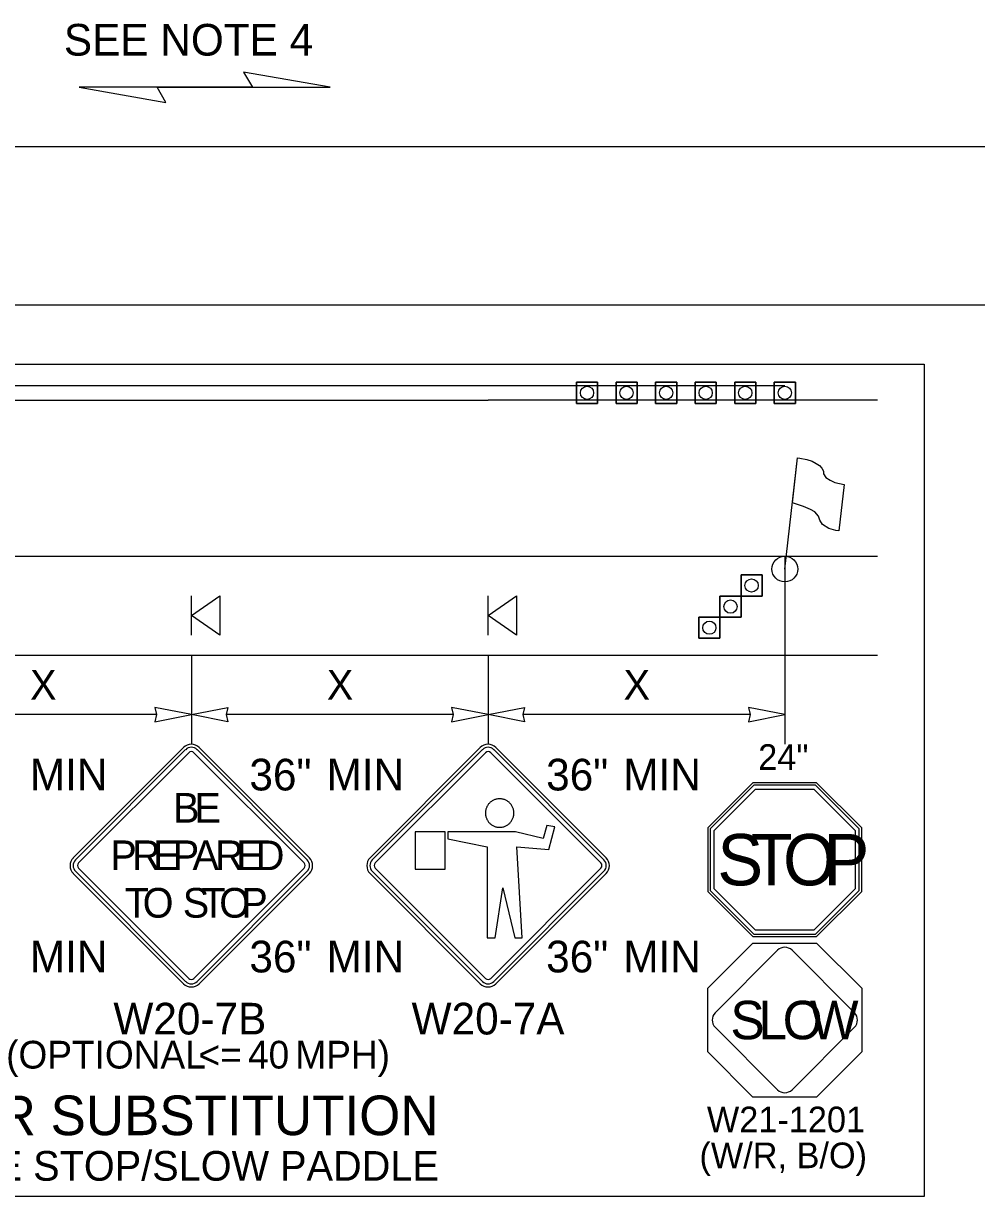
# Model space of a CAD drawing. Extents: x 99999.1 to 100095.7, y 99995 to 100010.7.
# Drawn here: x 100046.834 to 100049.243, y 100003.48 to 100006.443 of the extents above; entities that cross this region are included whole.
import ezdxf

# ---------------------------------------------------------------- set-up
doc = ezdxf.new("R2010")
doc.units = 0
for name, color, linetype in [('RD_ED_ShoulderPavedEdge', 7, 'Continuous'), ('RD_MK_LineDblYellowCenter', 7, 'Continuous'), ('RD_MK_LineEdgeWhite', 7, 'Continuous'), ('RD_MK_LineNoPass', 7, 'Continuous'), ('RD_MK_LineSkipCenter', 7, 'Continuous'), ('SH_DE_DetailHeading2Text', 7, 'Continuous'), ('TR_SN_ConstructionSigns', 7, 'Continuous'), ('TR_WZ_FlaggingStation', 7, 'Continuous'), ('TR_WZ_PortableSignMountBlk-Org', 7, 'Continuous'), ('TR_WZ_TrafficCone', 7, 'Continuous'), ('TR_WZ_WorkZoneDetails', 7, 'Continuous'), ('TR_WZ_WorkZoneTextCurrent', 7, 'Continuous')]:
    doc.layers.add(name, color=color, linetype=linetype)

msp = doc.modelspace()

# ---------------------------------------------------------------- linework, layer by layer
at = {"layer": 'RD_ED_ShoulderPavedEdge'}
for p, q in [((100040.1076, 100005.7323), (100055.6424, 100005.7323)), ((100045.4994, 100004.8473), (100048.9925, 100004.8473))]:
    msp.add_line(p, q, dxfattribs=at)
at = {"layer": 'RD_MK_LineDblYellowCenter'}
for p, q in [((100045.4994, 100005.5286), (100048.0081, 100005.5286)), ((100045.4994, 100005.4911), (100048.0081, 100005.4911))]:
    msp.add_line(p, q, dxfattribs=at)
at = {"layer": 'RD_MK_LineEdgeWhite'}
for p, q in [((100040.1076, 100006.1323), (100055.6424, 100006.1323)), ((100045.4994, 100005.0973), (100048.9925, 100005.0973))]:
    msp.add_line(p, q, dxfattribs=at)
at = {"layer": 'RD_MK_LineNoPass'}
msp.add_line((100048.0081, 100005.5286), (100048.7581, 100005.5286), dxfattribs=at)
at = {"layer": 'RD_MK_LineSkipCenter'}
msp.add_lwpolyline([(100048.9925, 100005.4911), (100048.0081, 100005.4911)], dxfattribs=at)
at = {"layer": 'TR_SN_ConstructionSigns'}
for p, q in [((100047.2382, 100004.6141), (100046.9598, 100004.3357)), ((100047.2437, 100004.6086), (100046.9653, 100004.3301)), ((100047.5509, 100004.3301), (100047.2724, 100004.6086)), ((100047.5564, 100004.3357), (100047.278, 100004.6141)), ((100047.9882, 100004.6141), (100047.7098, 100004.3357)), ((100047.9937, 100004.6086), (100047.7153, 100004.3301)), ((100048.3009, 100004.3301), (100048.0224, 100004.6086)), ((100048.3064, 100004.3357), (100048.028, 100004.6141)), ((100046.973, 100004.3224), (100047.2515, 100004.6008)), ((100047.2647, 100004.6008), (100047.5431, 100004.3224)), ((100047.723, 100004.3224), (100048.0015, 100004.6008)), ((100048.0147, 100004.6008), (100048.2931, 100004.3224)), ((100048.6775, 100004.5251), (100048.5636, 100004.4113)), ((100048.68, 100004.5191), (100048.5697, 100004.4087)), ((100048.8385, 100004.5251), (100048.6775, 100004.5251)), ((100048.836, 100004.5191), (100048.68, 100004.5191)), ((100048.9463, 100004.4087), (100048.836, 100004.5191)), ((100048.9524, 100004.4113), (100048.8385, 100004.5251)), ((100048.5798, 100004.4046), (100048.6842, 100004.5089)), ((100048.6842, 100004.5089), (100048.8318, 100004.5089)), ((100048.8318, 100004.5089), (100048.9362, 100004.4046)), ((100048.0025, 100004.458), (100048.0021, 100004.4561)), ((100048.0031, 100004.4598), (100048.0025, 100004.458)), ((100048.0037, 100004.4616), (100048.0031, 100004.4598)), ((100048.0045, 100004.4634), (100048.0037, 100004.4616)), ((100048.0053, 100004.4651), (100048.0045, 100004.4634)), ((100048.0062, 100004.4668), (100048.0053, 100004.4651)), ((100048.0073, 100004.4685), (100048.0062, 100004.4668)), ((100048.0083, 100004.47), (100048.0073, 100004.4685)), ((100048.0095, 100004.4715), (100048.0083, 100004.47)), ((100048.0108, 100004.473), (100048.0095, 100004.4715)), ((100048.0122, 100004.4743), (100048.0108, 100004.473)), ((100048.0135, 100004.4756), (100048.0122, 100004.4743)), ((100048.015, 100004.4768), (100048.0135, 100004.4756)), ((100048.0165, 100004.478), (100048.015, 100004.4768)), ((100048.0182, 100004.479), (100048.0165, 100004.478)), ((100048.0198, 100004.48), (100048.0182, 100004.479)), ((100048.0215, 100004.4809), (100048.0198, 100004.48)), ((100048.0232, 100004.4817), (100048.0215, 100004.4809)), ((100048.025, 100004.4824), (100048.0232, 100004.4817)), ((100048.0269, 100004.483), (100048.025, 100004.4824)), ((100048.0287, 100004.4835), (100048.0269, 100004.483)), ((100048.0306, 100004.4839), (100048.0287, 100004.4835)), ((100048.0325, 100004.4842), (100048.0306, 100004.4839)), ((100048.0344, 100004.4844), (100048.0325, 100004.4842)), ((100048.0363, 100004.4845), (100048.0344, 100004.4844)), ((100048.0382, 100004.4845), (100048.0363, 100004.4845)), ((100048.0401, 100004.4844), (100048.0382, 100004.4845)), ((100048.0421, 100004.4842), (100048.0401, 100004.4844)), ((100048.0439, 100004.4839), (100048.0421, 100004.4842)), ((100048.0458, 100004.4835), (100048.0439, 100004.4839)), ((100048.0476, 100004.483), (100048.0458, 100004.4835)), ((100048.0495, 100004.4824), (100048.0476, 100004.483)), ((100048.0513, 100004.4817), (100048.0495, 100004.4824)), ((100048.053, 100004.4809), (100048.0513, 100004.4817)), ((100048.0547, 100004.48), (100048.053, 100004.4809)), ((100048.0564, 100004.479), (100048.0547, 100004.48)), ((100048.058, 100004.478), (100048.0564, 100004.479)), ((100048.0595, 100004.4768), (100048.058, 100004.478)), ((100048.061, 100004.4756), (100048.0595, 100004.4768)), ((100048.0624, 100004.4743), (100048.061, 100004.4756)), ((100048.0637, 100004.473), (100048.0624, 100004.4743)), ((100048.065, 100004.4715), (100048.0637, 100004.473)), ((100048.0661, 100004.47), (100048.065, 100004.4715)), ((100048.0673, 100004.4685), (100048.0661, 100004.47)), ((100048.0683, 100004.4668), (100048.0673, 100004.4685)), ((100048.0692, 100004.4651), (100048.0683, 100004.4668)), ((100048.07, 100004.4634), (100048.0692, 100004.4651)), ((100048.0708, 100004.4616), (100048.07, 100004.4634)), ((100048.0715, 100004.4598), (100048.0708, 100004.4616)), ((100048.072, 100004.458), (100048.0715, 100004.4598)), ((100048.0725, 100004.4561), (100048.072, 100004.458)), ((100048.0015, 100004.4523), (100048.0013, 100004.4504)), ((100048.0013, 100004.4504), (100048.0013, 100004.4485)), ((100048.0013, 100004.4485), (100048.0013, 100004.4466)), ((100048.0013, 100004.4466), (100048.0015, 100004.4447)), ((100048.0017, 100004.4543), (100048.0015, 100004.4523)), ((100048.0015, 100004.4447), (100048.0017, 100004.4428)), ((100048.0021, 100004.4561), (100048.0017, 100004.4543)), ((100048.0017, 100004.4428), (100048.0021, 100004.4409)), ((100048.0021, 100004.4409), (100048.0025, 100004.439)), ((100048.0025, 100004.439), (100048.0031, 100004.4372)), ((100048.0031, 100004.4372), (100048.0037, 100004.4354)), ((100048.0037, 100004.4354), (100048.0045, 100004.4336)), ((100048.0045, 100004.4336), (100048.0053, 100004.4319)), ((100048.0053, 100004.4319), (100048.0062, 100004.4302)), ((100048.0062, 100004.4302), (100048.0073, 100004.4286)), ((100048.0073, 100004.4286), (100048.0083, 100004.427)), ((100048.0083, 100004.427), (100048.0095, 100004.4255)), ((100048.065, 100004.4255), (100048.0661, 100004.427)), ((100048.0661, 100004.427), (100048.0673, 100004.4286)), ((100048.0673, 100004.4286), (100048.0683, 100004.4302)), ((100048.0683, 100004.4302), (100048.0692, 100004.4319)), ((100048.0692, 100004.4319), (100048.07, 100004.4336)), ((100048.07, 100004.4336), (100048.0708, 100004.4354)), ((100048.0708, 100004.4354), (100048.0715, 100004.4372)), ((100048.0715, 100004.4372), (100048.072, 100004.439)), ((100048.072, 100004.439), (100048.0725, 100004.4409)), ((100048.0728, 100004.4543), (100048.0725, 100004.4561)), ((100048.0725, 100004.4409), (100048.0728, 100004.4428)), ((100048.0731, 100004.4523), (100048.0728, 100004.4543)), ((100048.0728, 100004.4428), (100048.0731, 100004.4447)), ((100048.0732, 100004.4504), (100048.0731, 100004.4523)), ((100048.0731, 100004.4447), (100048.0732, 100004.4466)), ((100048.0733, 100004.4485), (100048.0732, 100004.4504)), ((100048.0732, 100004.4466), (100048.0733, 100004.4485)), ((100047.8238, 100004.4012), (100047.8238, 100004.3065)), ((100047.8992, 100004.4012), (100047.8238, 100004.4012)), ((100047.8992, 100004.3065), (100047.8992, 100004.4012)), ((100048.0775, 100004.4012), (100047.9062, 100004.4012)), ((100047.9062, 100004.4012), (100047.9062, 100004.3831)), ((100048.0095, 100004.4255), (100048.0108, 100004.4241)), ((100048.0108, 100004.4241), (100048.0122, 100004.4227)), ((100048.0122, 100004.4227), (100048.0135, 100004.4214)), ((100048.0135, 100004.4214), (100048.015, 100004.4202)), ((100048.015, 100004.4202), (100048.0165, 100004.419)), ((100048.0165, 100004.419), (100048.0182, 100004.418)), ((100048.0182, 100004.418), (100048.0198, 100004.417)), ((100048.0198, 100004.417), (100048.0215, 100004.4161)), ((100048.0215, 100004.4161), (100048.0232, 100004.4153)), ((100048.0232, 100004.4153), (100048.025, 100004.4146)), ((100048.025, 100004.4146), (100048.0269, 100004.414)), ((100048.0269, 100004.414), (100048.0287, 100004.4135)), ((100048.0287, 100004.4135), (100048.0306, 100004.4131)), ((100048.0306, 100004.4131), (100048.0325, 100004.4128)), ((100048.0325, 100004.4128), (100048.0344, 100004.4126)), ((100048.0344, 100004.4126), (100048.0363, 100004.4125)), ((100048.0363, 100004.4125), (100048.0382, 100004.4125)), ((100048.0382, 100004.4125), (100048.0401, 100004.4126)), ((100048.0401, 100004.4126), (100048.0421, 100004.4128)), ((100048.0421, 100004.4128), (100048.0439, 100004.4131)), ((100048.0439, 100004.4131), (100048.0458, 100004.4135)), ((100048.0458, 100004.4135), (100048.0476, 100004.414)), ((100048.0476, 100004.414), (100048.0495, 100004.4146)), ((100048.0495, 100004.4146), (100048.0513, 100004.4153)), ((100048.0513, 100004.4153), (100048.053, 100004.4161)), ((100048.053, 100004.4161), (100048.0547, 100004.417)), ((100048.0547, 100004.417), (100048.0564, 100004.418)), ((100048.0564, 100004.418), (100048.058, 100004.419)), ((100048.058, 100004.419), (100048.0595, 100004.4202)), ((100048.0595, 100004.4202), (100048.061, 100004.4214)), ((100048.061, 100004.4214), (100048.0624, 100004.4227)), ((100048.0624, 100004.4227), (100048.0637, 100004.4241)), ((100048.0637, 100004.4241), (100048.065, 100004.4255)), ((100048.1471, 100004.3841), (100048.0775, 100004.4012)), ((100048.1568, 100004.4169), (100048.1471, 100004.3841)), ((100048.1767, 100004.4133), (100048.1568, 100004.4169)), ((100048.1617, 100004.3565), (100048.1767, 100004.4133)), ((100048.5636, 100004.4113), (100048.5636, 100004.2502)), ((100048.5697, 100004.4087), (100048.5697, 100004.2527)), ((100048.5798, 100004.2569), (100048.5798, 100004.4046)), ((100048.9362, 100004.4046), (100048.9362, 100004.2569)), ((100048.9463, 100004.2527), (100048.9463, 100004.4087)), ((100048.9524, 100004.2502), (100048.9524, 100004.4113)), ((100047.9062, 100004.3831), (100048.0057, 100004.3633)), ((100048.0057, 100004.3633), (100048.0057, 100004.133)), ((100048.0938, 100004.133), (100048.0807, 100004.3634)), ((100048.0807, 100004.3634), (100048.1617, 100004.3565)), ((100047.2515, 100004.0307), (100046.973, 100004.3092)), ((100047.5431, 100004.3092), (100047.2647, 100004.0307)), ((100048.0015, 100004.0307), (100047.723, 100004.3092)), ((100048.2931, 100004.3092), (100048.0147, 100004.0307)), ((100046.9598, 100004.2959), (100047.2382, 100004.0175)), ((100046.9653, 100004.3014), (100047.2437, 100004.023)), ((100047.2724, 100004.023), (100047.5509, 100004.3014)), ((100047.278, 100004.0175), (100047.5564, 100004.2959)), ((100047.7098, 100004.2959), (100047.9882, 100004.0175)), ((100047.7153, 100004.3014), (100047.9937, 100004.023)), ((100047.8238, 100004.3065), (100047.8992, 100004.3065)), ((100048.0224, 100004.023), (100048.3009, 100004.3014)), ((100048.028, 100004.0175), (100048.3064, 100004.2959)), ((100048.0259, 100004.133), (100048.0455, 100004.2597)), ((100048.0455, 100004.2597), (100048.0758, 100004.133)), ((100048.5636, 100004.2502), (100048.6775, 100004.1363)), ((100048.5697, 100004.2527), (100048.68, 100004.1424)), ((100048.6842, 100004.1525), (100048.5798, 100004.2569)), ((100048.9362, 100004.2569), (100048.8318, 100004.1525)), ((100048.836, 100004.1424), (100048.9463, 100004.2527)), ((100048.8385, 100004.1363), (100048.9524, 100004.2502)), ((100048.0057, 100004.133), (100048.0259, 100004.133)), ((100048.0758, 100004.133), (100048.0938, 100004.133)), ((100048.6775, 100004.1363), (100048.8385, 100004.1363)), ((100048.68, 100004.1424), (100048.836, 100004.1424)), ((100048.8318, 100004.1525), (100048.6842, 100004.1525)), ((100048.7397, 100004.1018), (100048.5819, 100003.9441)), ((100048.9341, 100003.9441), (100048.7763, 100004.1018)), ((100048.5819, 100003.9074), (100048.7397, 100003.7497)), ((100048.7763, 100003.7497), (100048.9341, 100003.9074))]:
    msp.add_line(p, q, dxfattribs=at)
msp.add_lwpolyline([(100048.9524, 100004.0063), (100048.9524, 100003.8452), (100048.8385, 100003.7313), (100048.6775, 100003.7313), (100048.5636, 100003.8452), (100048.5636, 100004.0063), (100048.6775, 100004.1201), (100048.8385, 100004.1201)], close=True, dxfattribs=at)
for centre, radius, start, end in [((100047.2581, 100004.5942), 0.0281, 45, 135), ((100047.2581, 100004.5942), 0.0203, 45, 135), ((100048.0081, 100004.5942), 0.0281, 45, 135), ((100048.0081, 100004.5942), 0.0203, 45, 135), ((100047.2581, 100004.5942), 0.00937, 45, 135), ((100048.0081, 100004.5942), 0.00937, 45, 135), ((100046.9797, 100004.3158), 0.0281, 135, 225), ((100046.9797, 100004.3158), 0.0203, 135, 225), ((100046.9797, 100004.3158), 0.00937, 135, 225), ((100047.5365, 100004.3158), 0.00937, 315, 45), ((100047.5365, 100004.3158), 0.0203, 315, 45), ((100047.5365, 100004.3158), 0.0281, 315, 45), ((100047.7297, 100004.3158), 0.0281, 135, 225), ((100047.7297, 100004.3158), 0.0203, 135, 225), ((100047.7297, 100004.3158), 0.00937, 135, 225), ((100048.2865, 100004.3158), 0.00937, 315, 45), ((100048.2865, 100004.3158), 0.0203, 315, 45), ((100048.2865, 100004.3158), 0.0281, 315, 45), ((100048.758, 100004.0835), 0.0259, 45, 135), ((100047.2581, 100004.0374), 0.0281, 225, 315), ((100047.2581, 100004.0374), 0.0203, 225, 315), ((100047.2581, 100004.0374), 0.00937, 225, 315), ((100048.0081, 100004.0374), 0.0281, 225, 315), ((100048.0081, 100004.0374), 0.0203, 225, 315), ((100048.0081, 100004.0374), 0.00937, 225, 315), ((100048.6003, 100003.9257), 0.0259, 135, 225), ((100048.9157, 100003.9257), 0.0259, 315, 45), ((100048.758, 100003.768), 0.0259, 225, 315)]:
    msp.add_arc(centre, radius, start, end, dxfattribs=at)
at = {"layer": 'TR_WZ_FlaggingStation'}
for p, q in [((100048.7581, 100005.0648), (100048.7901, 100005.3458)), ((100048.7771, 100005.2317), (100048.7902, 100005.3461)), ((100048.9081, 100005.2783), (100048.8948, 100005.1611)), ((100048.7771, 100005.2317), (100048.7771, 100005.2317))]:
    msp.add_line(p, q, dxfattribs=at)
for points in [[(100048.7902, 100005.3461), (100048.7959, 100005.3448), (100048.8137, 100005.3414), (100048.8276, 100005.3372), (100048.8372, 100005.3311), (100048.8458, 100005.3264), (100048.8515, 100005.3196), (100048.8557, 100005.3117), (100048.8562, 100005.3055), (100048.8616, 100005.2963), (100048.8724, 100005.2889), (100048.8848, 100005.2837), (100048.9081, 100005.2783)], [(100048.8948, 100005.1611), (100048.8867, 100005.1625), (100048.869, 100005.1671), (100048.8533, 100005.1776), (100048.8468, 100005.1882), (100048.8429, 100005.1985), (100048.8338, 100005.2094), (100048.8229, 100005.2156), (100048.8055, 100005.2227), (100048.7771, 100005.2317)]]:
    msp.add_lwpolyline(points, dxfattribs=at)
msp.add_circle((100048.7581, 100005.0648), 0.0325, dxfattribs=at)
at = {"layer": 'TR_WZ_PortableSignMountBlk-Org'}
for p, q in [((100047.2581, 100004.8974), (100047.2581, 100004.9974)), ((100048.0081, 100004.8974), (100048.0081, 100004.9974))]:
    msp.add_line(p, q, dxfattribs=at)
for points in [[(100047.2581, 100004.9473), (100047.3299, 100004.9974), (100047.3299, 100004.8974)], [(100048.0081, 100004.9473), (100048.0799, 100004.9974), (100048.0799, 100004.8974)]]:
    msp.add_lwpolyline(points, close=True, dxfattribs=at)
at = {"layer": 'TR_WZ_TrafficCone'}
for points in [[(100048.2848, 100005.5365), (100048.2314, 100005.5365), (100048.2314, 100005.4832), (100048.2848, 100005.4832), (100048.2848, 100005.5365)], [(100048.2848, 100005.4832), (100048.2314, 100005.4832), (100048.2314, 100005.5365), (100048.2848, 100005.5365), (100048.2848, 100005.4832)], [(100048.3848, 100005.5365), (100048.3314, 100005.5365), (100048.3314, 100005.4832), (100048.3848, 100005.4832), (100048.3848, 100005.5365)], [(100048.3848, 100005.4832), (100048.3314, 100005.4832), (100048.3314, 100005.5365), (100048.3848, 100005.5365), (100048.3848, 100005.4832)], [(100048.4848, 100005.5365), (100048.4314, 100005.5365), (100048.4314, 100005.4832), (100048.4848, 100005.4832), (100048.4848, 100005.5365)], [(100048.4848, 100005.4832), (100048.4314, 100005.4832), (100048.4314, 100005.5365), (100048.4848, 100005.5365), (100048.4848, 100005.4832)], [(100048.5848, 100005.5365), (100048.5314, 100005.5365), (100048.5314, 100005.4832), (100048.5848, 100005.4832), (100048.5848, 100005.5365)], [(100048.5848, 100005.4832), (100048.5314, 100005.4832), (100048.5314, 100005.5365), (100048.5848, 100005.5365), (100048.5848, 100005.4832)], [(100048.6848, 100005.5365), (100048.6314, 100005.5365), (100048.6314, 100005.4832), (100048.6848, 100005.4832), (100048.6848, 100005.5365)], [(100048.6848, 100005.4832), (100048.6314, 100005.4832), (100048.6314, 100005.5365), (100048.6848, 100005.5365), (100048.6848, 100005.4832)], [(100048.7848, 100005.5365), (100048.7314, 100005.5365), (100048.7314, 100005.4832), (100048.7848, 100005.4832), (100048.7848, 100005.5365)], [(100048.7848, 100005.4832), (100048.7314, 100005.4832), (100048.7314, 100005.5365), (100048.7848, 100005.5365), (100048.7848, 100005.4832)], [(100048.6474, 100005.05), (100048.7008, 100005.05), (100048.7008, 100004.9967), (100048.6474, 100004.9967), (100048.6474, 100005.05)], [(100048.6474, 100004.9967), (100048.7008, 100004.9967), (100048.7008, 100005.05), (100048.6474, 100005.05), (100048.6474, 100004.9967)], [(100048.5941, 100004.9967), (100048.6474, 100004.9967), (100048.6474, 100004.9433), (100048.5941, 100004.9433), (100048.5941, 100004.9967)], [(100048.5941, 100004.9433), (100048.6474, 100004.9433), (100048.6474, 100004.9967), (100048.5941, 100004.9967), (100048.5941, 100004.9433)], [(100048.5408, 100004.9433), (100048.5941, 100004.9433), (100048.5941, 100004.89), (100048.5408, 100004.89), (100048.5408, 100004.9433)], [(100048.5408, 100004.89), (100048.5941, 100004.89), (100048.5941, 100004.9433), (100048.5408, 100004.9433), (100048.5408, 100004.89)]]:
    msp.add_lwpolyline(points, dxfattribs=at)
for centre in [(100048.2581, 100005.5098), (100048.3581, 100005.5098), (100048.4581, 100005.5098), (100048.5581, 100005.5098), (100048.6581, 100005.5098), (100048.7581, 100005.5098), (100048.6741, 100005.0233), (100048.6208, 100004.97), (100048.5674, 100004.9167)]:
    msp.add_circle(centre, 0.0167, dxfattribs=at)
at = {"layer": 'TR_WZ_WorkZoneDetails'}
for p, q in [((100047.1713, 100006.2816), (100047.4124, 100006.2816)), ((100047.4124, 100006.2816), (100047.1713, 100006.2816)), ((100048.7581, 100005.0973), (100048.7581, 100004.6223)), ((100047.2581, 100004.8473), (100047.2581, 100004.6223)), ((100048.0081, 100004.8473), (100048.0081, 100004.6223)), ((100047.1702, 100004.6973), (100046.596, 100004.6973)), ((100047.9202, 100004.6973), (100047.346, 100004.6973)), ((100048.6702, 100004.6973), (100048.096, 100004.6973))]:
    msp.add_line(p, q, dxfattribs=at)
for points in [[(100047.609, 100006.2816), (100047.3901, 100006.3202), (100047.4124, 100006.2816)], [(100046.9748, 100006.2816), (100047.1936, 100006.243), (100047.1713, 100006.2816)], [(100047.2581, 100004.6973), (100047.1659, 100004.7154), (100047.1702, 100004.6973), (100047.1659, 100004.6793)], [(100047.2581, 100004.6973), (100047.3502, 100004.7154), (100047.346, 100004.6973), (100047.3502, 100004.6793)], [(100048.0081, 100004.6973), (100047.9159, 100004.7154), (100047.9202, 100004.6973), (100047.9159, 100004.6793)], [(100048.0081, 100004.6973), (100048.1002, 100004.7154), (100048.096, 100004.6973), (100048.1002, 100004.6793)], [(100048.7581, 100004.6973), (100048.6659, 100004.7154), (100048.6702, 100004.6973), (100048.6659, 100004.6793)]]:
    msp.add_lwpolyline(points, close=True, dxfattribs=at)
at = {"layer": 'TR_WZ_WorkZoneTextCurrent'}
msp.add_lwpolyline([(100045.3092, 100005.5823), (100049.1102, 100005.5823), (100049.1102, 100003.4799), (100045.3092, 100003.4799)], close=True, dxfattribs=at)

# ---------------------------------------------------------------- texts
at = {"layer": 'SH_DE_DetailHeading2Text'}
msp.add_text('HUMAN FLAGGER SUBSTITUTION', height=0.1, rotation=360, dxfattribs=at).set_placement((100045.6986, 100003.6349))
at = {"layer": 'TR_SN_ConstructionSigns'}
for s, height, p in [('24"', 0.0648, (100048.6908, 100004.5575)), ('B', 0.075, (100047.2118, 100004.4243)), ('E', 0.075, (100047.2661, 100004.4243)), ('S', 0.1296, (100048.5876, 100004.2659)), ('O', 0.1296, (100048.7535, 100004.2659)), ('P', 0.075, (100047.0532, 100004.3043)), ('R', 0.075, (100047.1084, 100004.3043)), ('E', 0.075, (100047.1616, 100004.3043)), ('P', 0.075, (100047.2111, 100004.3043)), ('A', 0.075, (100047.261, 100004.3043)), ('R', 0.075, (100047.3183, 100004.3043)), ('E', 0.075, (100047.3715, 100004.3043)), ('D', 0.075, (100047.421, 100004.3043)), ('T', 0.1296, (100048.6718, 100004.2659)), ('P', 0.1296, (100048.8559, 100004.2659)), ('T', 0.075, (100047.0898, 100004.1843)), ('O', 0.075, (100047.135, 100004.1843)), ('S', 0.075, (100047.2364, 100004.1843)), ('T', 0.075, (100047.2835, 100004.1843)), ('O', 0.075, (100047.3286, 100004.1843)), ('P', 0.075, (100047.3843, 100004.1843)), ('S', 0.0972, (100048.6205, 100003.8771)), ('L', 0.0972, (100048.6914, 100003.8771)), ('O', 0.0972, (100048.7527, 100003.8771)), ('W', 0.0972, (100048.8217, 100003.8771))]:
    msp.add_text(s, height=height, dxfattribs=at).set_placement(p)
for s, height, p in [('MIN', 0.08, (100046.8499, 100004.5056)), ('36"', 0.08, (100047.4048, 100004.5056)), ('MIN', 0.08, (100047.5999, 100004.5056)), ('36"', 0.08, (100048.1548, 100004.5056)), ('MIN', 0.08, (100048.3499, 100004.5056)), ('MIN', 0.08, (100046.8499, 100004.046)), ('36"', 0.08, (100047.4048, 100004.046)), ('MIN', 0.08, (100047.5999, 100004.046)), ('36"', 0.08, (100048.1548, 100004.046)), ('MIN', 0.08, (100048.3499, 100004.046)), ('W20-7B', 0.08, (100047.0611, 100003.8892)), ('W20-7A', 0.08, (100047.8148, 100003.8892)), ('(OPTIONAL', 0.07, (100046.79, 100003.8032)), ('40', 0.07, (100047.4013, 100003.8032)), ('MPH)', 0.07, (100047.521, 100003.8032)), ('<=', 0.07, (100047.2763, 100003.8032)), ('W21-1201', 0.0648, (100048.5611, 100003.6422)), ('(W/R, B/O)', 0.0648, (100048.5423, 100003.5515))]:
    msp.add_text(s, height=height, rotation=360, dxfattribs=at).set_placement(p)
at = {"layer": 'TR_WZ_WorkZoneTextCurrent'}
for s, height, p in [('SEE NOTE 4', 0.08, (100046.9359, 100006.3616)), ('UPDATE SIGNAGE & USE STOP/SLOW PADDLE', 0.075, (100045.6099, 100003.5199))]:
    msp.add_text(s, height=height, dxfattribs=at).set_placement(p)
for p in [(100046.8505, 100004.7348), (100047.6005, 100004.7348), (100048.3505, 100004.7348)]:
    msp.add_text('X', height=0.075, rotation=360, dxfattribs=at).set_placement(p)

doc.saveas('drawing.dxf')
